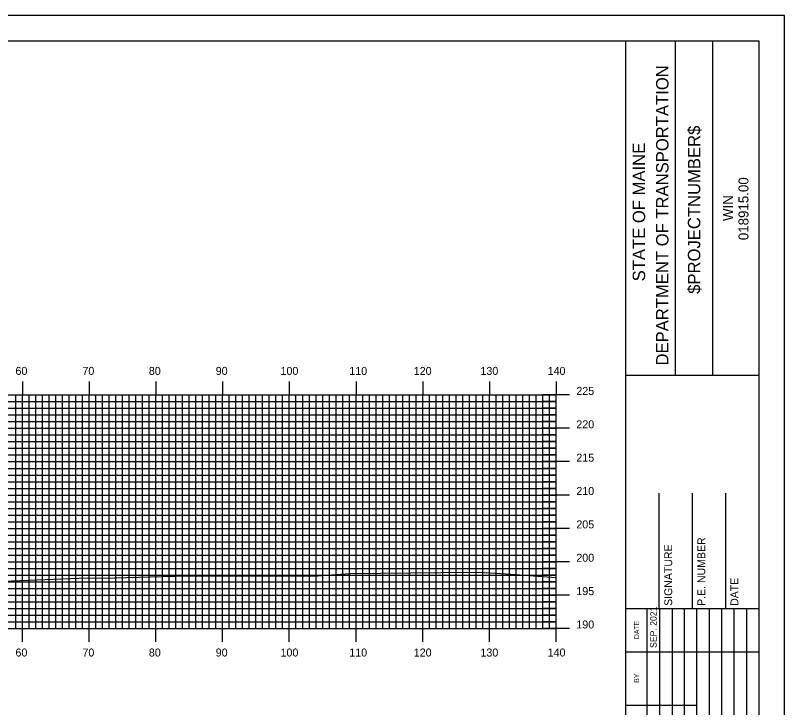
# Model space of a CAD drawing. Extents: x 1811767 to 1812110, y 442591 to 442811.
# Drawn here: x 1811991.9 to 1812107.1, y 442706.8 to 442810.5 of the extents above; entities that cross this region are included whole.
import ezdxf

# ---------------------------------------------------------------- set-up
doc = ezdxf.new("R2010")
doc.units = 0
for name, color, linetype in [('BORDER', 7, 'Continuous'), ('H_V ANNOTATION', 7, 'Continuous'), ('MAJOR', 7, 'Continuous'), ('MINOR', 7, 'Continuous'), ('PLOT BOUNDARY', 7, 'Continuous'), ('S_Roadway_Centerline', 7, 'Continuous')]:
    doc.layers.add(name, color=color, linetype=linetype)

msp = doc.modelspace()

# ---------------------------------------------------------------- linework, layer by layer
at = {"layer": 'BORDER'}
for p, q in [((1812083.32, 442596.67), (1812083.32, 442806.67)), ((1812090.77, 442756.66), (1812090.77, 442806.66)), ((1812096.36, 442756.66), (1812096.36, 442806.66)), ((1812083.32, 442756.65), (1812103.32, 442756.65)), ((1812088.32, 442721.67), (1812088.32, 442738.97)), ((1812093.32, 442721.67), (1812093.32, 442738.97)), ((1812098.32, 442721.67), (1812098.32, 442738.97)), ((1812083.32, 442721.67), (1812103.32, 442721.67))]:
    msp.add_line(p, q, dxfattribs=at)
msp.add_lwpolyline([(1811783.32, 442596.67), (1812103.32, 442596.67), (1812103.32, 442806.67), (1811783.32, 442806.67)], close=True, dxfattribs=at)
for points in [[(1812086.55, 442715.17), (1812086.55, 442721.67)], [(1812088.41, 442686.68), (1812088.41, 442721.67)], [(1812090.27, 442721.67), (1812090.27, 442686.68)], [(1812092.14, 442686.68), (1812092.14, 442721.67)], [(1812094, 442686.68), (1812094, 442721.67)], [(1812095.86, 442686.68), (1812095.86, 442721.67)], [(1812097.73, 442686.68), (1812097.73, 442721.67)], [(1812099.59, 442686.68), (1812099.59, 442721.67)], [(1812101.45, 442686.68), (1812101.45, 442721.67)], [(1812086.55, 442686.68), (1812086.55, 442720.26)], [(1812083.32, 442715.17), (1812103.32, 442715.17)], [(1812083.32, 442707.17), (1812086.55, 442707.17)], [(1812086.55, 442707.17), (1812094, 442707.17)]]:
    msp.add_lwpolyline(points, dxfattribs=at)
at = {"layer": 'MAJOR'}
for p, q in [((1811992.92, 442755.67), (1811992.92, 442753.67)), ((1812002.92, 442755.67), (1812002.92, 442753.67)), ((1812012.92, 442755.67), (1812012.92, 442753.67)), ((1812022.92, 442755.67), (1812022.92, 442753.67)), ((1812032.92, 442755.67), (1812032.92, 442753.67)), ((1812042.92, 442755.67), (1812042.92, 442753.67)), ((1812052.92, 442755.67), (1812052.92, 442753.67)), ((1812062.92, 442755.67), (1812062.92, 442753.67)), ((1812072.92, 442755.67), (1812072.92, 442753.67)), ((1811792.92, 442753.67), (1812072.92, 442753.67)), ((1811792.92, 442753.67), (1812072.92, 442753.67)), ((1811992.92, 442718.67), (1811992.92, 442753.67)), ((1812002.92, 442718.67), (1812002.92, 442753.67)), ((1812012.92, 442718.67), (1812012.92, 442753.67)), ((1812022.92, 442718.67), (1812022.92, 442753.67)), ((1812032.92, 442718.67), (1812032.92, 442753.67)), ((1812042.92, 442718.67), (1812042.92, 442753.67)), ((1812052.92, 442718.67), (1812052.92, 442753.67)), ((1812062.92, 442718.67), (1812062.92, 442753.67)), ((1812074.92, 442753.67), (1812070.91, 442753.67)), ((1812072.92, 442718.67), (1812072.92, 442753.67)), ((1812072.92, 442718.67), (1812072.92, 442753.67)), ((1811792.92, 442748.67), (1812072.92, 442748.67)), ((1812074.92, 442748.67), (1812070.91, 442748.67)), ((1811792.92, 442743.67), (1812072.92, 442743.67)), ((1812074.92, 442743.67), (1812070.91, 442743.67)), ((1811792.92, 442738.67), (1812072.92, 442738.67)), ((1812074.92, 442738.67), (1812070.91, 442738.67)), ((1811792.92, 442733.67), (1812072.92, 442733.67)), ((1812074.92, 442733.67), (1812070.91, 442733.67)), ((1811792.92, 442728.67), (1812072.92, 442728.67)), ((1812074.92, 442728.67), (1812070.91, 442728.67)), ((1811792.92, 442723.67), (1812072.92, 442723.67)), ((1812074.92, 442723.67), (1812070.91, 442723.67)), ((1811792.92, 442718.67), (1812072.92, 442718.67)), ((1811792.92, 442718.67), (1812072.92, 442718.67)), ((1811992.92, 442716.66), (1811992.92, 442718.67)), ((1812002.92, 442716.66), (1812002.92, 442718.67)), ((1812012.92, 442716.66), (1812012.92, 442718.67)), ((1812022.92, 442716.66), (1812022.92, 442718.67)), ((1812032.92, 442716.66), (1812032.92, 442718.67)), ((1812042.92, 442716.66), (1812042.92, 442718.67)), ((1812052.92, 442716.66), (1812052.92, 442718.67)), ((1812062.92, 442716.66), (1812062.92, 442718.67)), ((1812074.92, 442718.67), (1812070.91, 442718.67)), ((1812072.92, 442716.66), (1812072.92, 442718.67))]:
    msp.add_line(p, q, dxfattribs=at)
at = {"layer": 'MINOR'}
for p, q in [((1811991.92, 442718.67), (1811991.92, 442753.67)), ((1811993.92, 442718.67), (1811993.92, 442753.67)), ((1811994.92, 442718.67), (1811994.92, 442753.67)), ((1811995.92, 442718.67), (1811995.92, 442753.67)), ((1811996.92, 442718.67), (1811996.92, 442753.67)), ((1811997.92, 442718.67), (1811997.92, 442753.67)), ((1811998.92, 442718.67), (1811998.92, 442753.67)), ((1811999.92, 442718.67), (1811999.92, 442753.67)), ((1812000.92, 442718.67), (1812000.92, 442753.67)), ((1812001.92, 442718.67), (1812001.92, 442753.67)), ((1812003.92, 442718.67), (1812003.92, 442753.67)), ((1812004.92, 442718.67), (1812004.92, 442753.67)), ((1812005.92, 442718.67), (1812005.92, 442753.67)), ((1812006.92, 442718.67), (1812006.92, 442753.67)), ((1812007.92, 442718.67), (1812007.92, 442753.67)), ((1812008.92, 442718.67), (1812008.92, 442753.67)), ((1812009.92, 442718.67), (1812009.92, 442753.67)), ((1812010.92, 442718.67), (1812010.92, 442753.67)), ((1812011.92, 442718.67), (1812011.92, 442753.67)), ((1812013.92, 442718.67), (1812013.92, 442753.67)), ((1812014.92, 442718.67), (1812014.92, 442753.67)), ((1812015.92, 442718.67), (1812015.92, 442753.67)), ((1812016.92, 442718.67), (1812016.92, 442753.67)), ((1812017.92, 442718.67), (1812017.92, 442753.67)), ((1812018.92, 442718.67), (1812018.92, 442753.67)), ((1812019.92, 442718.67), (1812019.92, 442753.67)), ((1812020.92, 442718.67), (1812020.92, 442753.67)), ((1812021.92, 442718.67), (1812021.92, 442753.67)), ((1812023.92, 442718.67), (1812023.92, 442753.67)), ((1812024.92, 442718.67), (1812024.92, 442753.67)), ((1812025.92, 442718.67), (1812025.92, 442753.67)), ((1812026.92, 442718.67), (1812026.92, 442753.67)), ((1812027.92, 442718.67), (1812027.92, 442753.67)), ((1812028.92, 442718.67), (1812028.92, 442753.67)), ((1812029.92, 442718.67), (1812029.92, 442753.67)), ((1812030.92, 442718.67), (1812030.92, 442753.67)), ((1812031.92, 442718.67), (1812031.92, 442753.67)), ((1812033.92, 442718.67), (1812033.92, 442753.67)), ((1812034.92, 442718.67), (1812034.92, 442753.67)), ((1812035.92, 442718.67), (1812035.92, 442753.67)), ((1812036.92, 442718.67), (1812036.92, 442753.67)), ((1812037.92, 442718.67), (1812037.92, 442753.67)), ((1812038.92, 442718.67), (1812038.92, 442753.67)), ((1812039.92, 442718.67), (1812039.92, 442753.67)), ((1812040.92, 442718.67), (1812040.92, 442753.67)), ((1812041.92, 442718.67), (1812041.92, 442753.67)), ((1812043.92, 442718.67), (1812043.92, 442753.67)), ((1812044.92, 442718.67), (1812044.92, 442753.67)), ((1812045.92, 442718.67), (1812045.92, 442753.67)), ((1812046.92, 442718.67), (1812046.92, 442753.67)), ((1812047.92, 442718.67), (1812047.92, 442753.67)), ((1812048.92, 442718.67), (1812048.92, 442753.67)), ((1812049.92, 442718.67), (1812049.92, 442753.67)), ((1812050.92, 442718.67), (1812050.92, 442753.67)), ((1812051.92, 442718.67), (1812051.92, 442753.67)), ((1812053.92, 442718.67), (1812053.92, 442753.67)), ((1812054.92, 442718.67), (1812054.92, 442753.67)), ((1812055.92, 442718.67), (1812055.92, 442753.67)), ((1812056.92, 442718.67), (1812056.92, 442753.67)), ((1812057.92, 442718.67), (1812057.92, 442753.67)), ((1812058.92, 442718.67), (1812058.92, 442753.67)), ((1812059.92, 442718.67), (1812059.92, 442753.67)), ((1812060.92, 442718.67), (1812060.92, 442753.67)), ((1812061.92, 442718.67), (1812061.92, 442753.67)), ((1812063.92, 442718.67), (1812063.92, 442753.67)), ((1812064.92, 442718.67), (1812064.92, 442753.67)), ((1812065.92, 442718.67), (1812065.92, 442753.67)), ((1812066.92, 442718.67), (1812066.92, 442753.67)), ((1812067.92, 442718.67), (1812067.92, 442753.67)), ((1812068.92, 442718.67), (1812068.92, 442753.67)), ((1812069.92, 442718.67), (1812069.92, 442753.67)), ((1812070.92, 442718.67), (1812070.92, 442753.67)), ((1812071.92, 442718.67), (1812071.92, 442753.67)), ((1811792.92, 442752.67), (1812072.92, 442752.67)), ((1812072.92, 442752.67), (1812070.91, 442752.67)), ((1811792.92, 442751.67), (1812072.92, 442751.67)), ((1812072.92, 442751.67), (1812070.91, 442751.67)), ((1811792.92, 442750.67), (1812072.92, 442750.67)), ((1812072.92, 442750.67), (1812070.91, 442750.67)), ((1811792.92, 442749.67), (1812072.92, 442749.67)), ((1812072.92, 442749.67), (1812070.91, 442749.67)), ((1811792.92, 442747.67), (1812072.92, 442747.67)), ((1812072.92, 442747.67), (1812070.91, 442747.67)), ((1811792.92, 442746.67), (1812072.92, 442746.67)), ((1812072.92, 442746.67), (1812070.91, 442746.67)), ((1811792.92, 442745.67), (1812072.92, 442745.67)), ((1812072.92, 442745.67), (1812070.91, 442745.67)), ((1811792.92, 442744.67), (1812072.92, 442744.67)), ((1812072.92, 442744.67), (1812070.91, 442744.67)), ((1811792.92, 442742.67), (1812072.92, 442742.67)), ((1812072.92, 442742.67), (1812070.91, 442742.67)), ((1811792.92, 442741.67), (1812072.92, 442741.67)), ((1812072.92, 442741.67), (1812070.91, 442741.67)), ((1811792.92, 442740.67), (1812072.92, 442740.67)), ((1811792.92, 442739.67), (1812072.92, 442739.67)), ((1812072.92, 442740.67), (1812070.91, 442740.67)), ((1812072.92, 442739.67), (1812070.91, 442739.67)), ((1811792.92, 442737.67), (1812072.92, 442737.67)), ((1812072.92, 442737.67), (1812070.91, 442737.67)), ((1811792.92, 442736.67), (1812072.92, 442736.67)), ((1812072.92, 442736.67), (1812070.91, 442736.67)), ((1811792.92, 442735.67), (1812072.92, 442735.67)), ((1812072.92, 442735.67), (1812070.91, 442735.67)), ((1811792.92, 442734.67), (1812072.92, 442734.67)), ((1812072.92, 442734.67), (1812070.91, 442734.67)), ((1811792.92, 442732.67), (1812072.92, 442732.67)), ((1812072.92, 442732.67), (1812070.91, 442732.67)), ((1811792.92, 442731.67), (1812072.92, 442731.67)), ((1812072.92, 442731.67), (1812070.91, 442731.67)), ((1811792.92, 442730.67), (1812072.92, 442730.67)), ((1812072.92, 442730.67), (1812070.91, 442730.67)), ((1811792.92, 442729.67), (1812072.92, 442729.67)), ((1812072.92, 442729.67), (1812070.91, 442729.67)), ((1811792.92, 442727.67), (1812072.92, 442727.67)), ((1812072.92, 442727.67), (1812070.91, 442727.67)), ((1811792.92, 442726.67), (1812072.92, 442726.67)), ((1812072.92, 442726.67), (1812070.91, 442726.67)), ((1811792.92, 442725.67), (1812072.92, 442725.67)), ((1811792.92, 442724.67), (1812072.92, 442724.67)), ((1812072.92, 442725.67), (1812070.91, 442725.67)), ((1812072.92, 442724.67), (1812070.91, 442724.67)), ((1811792.92, 442722.67), (1812072.92, 442722.67)), ((1812072.92, 442722.67), (1812070.91, 442722.67)), ((1811792.92, 442721.67), (1812072.92, 442721.67)), ((1812072.92, 442721.67), (1812070.91, 442721.67)), ((1811792.92, 442720.67), (1812072.92, 442720.67)), ((1812072.92, 442720.67), (1812070.91, 442720.67)), ((1811792.92, 442719.67), (1812072.92, 442719.67)), ((1812072.92, 442719.67), (1812070.91, 442719.67))]:
    msp.add_line(p, q, dxfattribs=at)
at = {"layer": 'PLOT BOUNDARY'}
msp.add_lwpolyline([(1811767.13, 442590.55), (1812107.13, 442590.55), (1812107.13, 442810.55), (1811767.13, 442810.55)], close=True, dxfattribs=at)
at = {"layer": 'S_Roadway_Centerline'}
msp.add_lwpolyline([(1811990.06, 442725.78), (1812001.38, 442726.22), (1812006.71, 442726.27), (1812017.52, 442726.54), (1812036.47, 442726.52), (1812042.04, 442726.91), (1812055.67, 442727.04), (1812061.29, 442727.09), (1812065.39, 442726.85), (1812072.92, 442726.3)], dxfattribs=at)

# ---------------------------------------------------------------- texts
at = {"layer": 'BORDER'}
for s, height, p in [('DEPARTMENT OF TRANSPORTATION', 1.8635, (1812089.73, 442758.08)), ('$PROJECTNUMBER$', 1.8635, (1812094.5, 442768.82)), ('STATE OF MAINE', 1.8635, (1812086.23, 442770.69)), ('018915.00', 1.491, (1812101.71, 442776.86)), ('WIN', 1.491, (1812099.39, 442779.73)), ('P.E. NUMBER', 1.1811, (1812095.24, 442722.06)), ('SIGNATURE', 1.181, (1812090.28, 442722.06)), ('DATE', 1.181, (1812100.2, 442722.06)), ('SEP. 2021', 0.969, (1812087.96, 442715.76)), ('DATE', 0.743, (1812085.32, 442717.08)), ('BY', 0.743, (1812085.32, 442710.54))]:
    msp.add_text(s, height=height, rotation=90, dxfattribs=at).set_placement(p)
at = {"layer": 'H_V ANNOTATION'}
for s, p in [('60', (1811991.89, 442756.67)), ('70', (1812001.92, 442756.67)), ('80', (1812011.87, 442756.67)), ('90', (1812021.89, 442756.67)), ('100', (1812031.6, 442756.67)), ('110', (1812041.9, 442756.67)), ('120', (1812051.56, 442756.67)), ('130', (1812061.55, 442756.67)), ('140', (1812071.62, 442756.67)), ('225', (1812075.92, 442753.67)), ('220', (1812075.92, 442748.67)), ('215', (1812075.92, 442743.67)), ('210', (1812075.92, 442738.67)), ('205', (1812075.92, 442733.67)), ('200', (1812075.92, 442728.67)), ('195', (1812075.92, 442723.67)), ('190', (1812075.92, 442718.67)), ('60', (1811991.89, 442714.47)), ('70', (1812001.92, 442714.47)), ('80', (1812011.87, 442714.47)), ('90', (1812021.89, 442714.47)), ('100', (1812031.6, 442714.47)), ('110', (1812041.9, 442714.47)), ('120', (1812051.56, 442714.47)), ('130', (1812061.55, 442714.47)), ('140', (1812071.62, 442714.47))]:
    msp.add_text(s, height=1.2, dxfattribs=at).set_placement(p)

doc.saveas('drawing.dxf')
